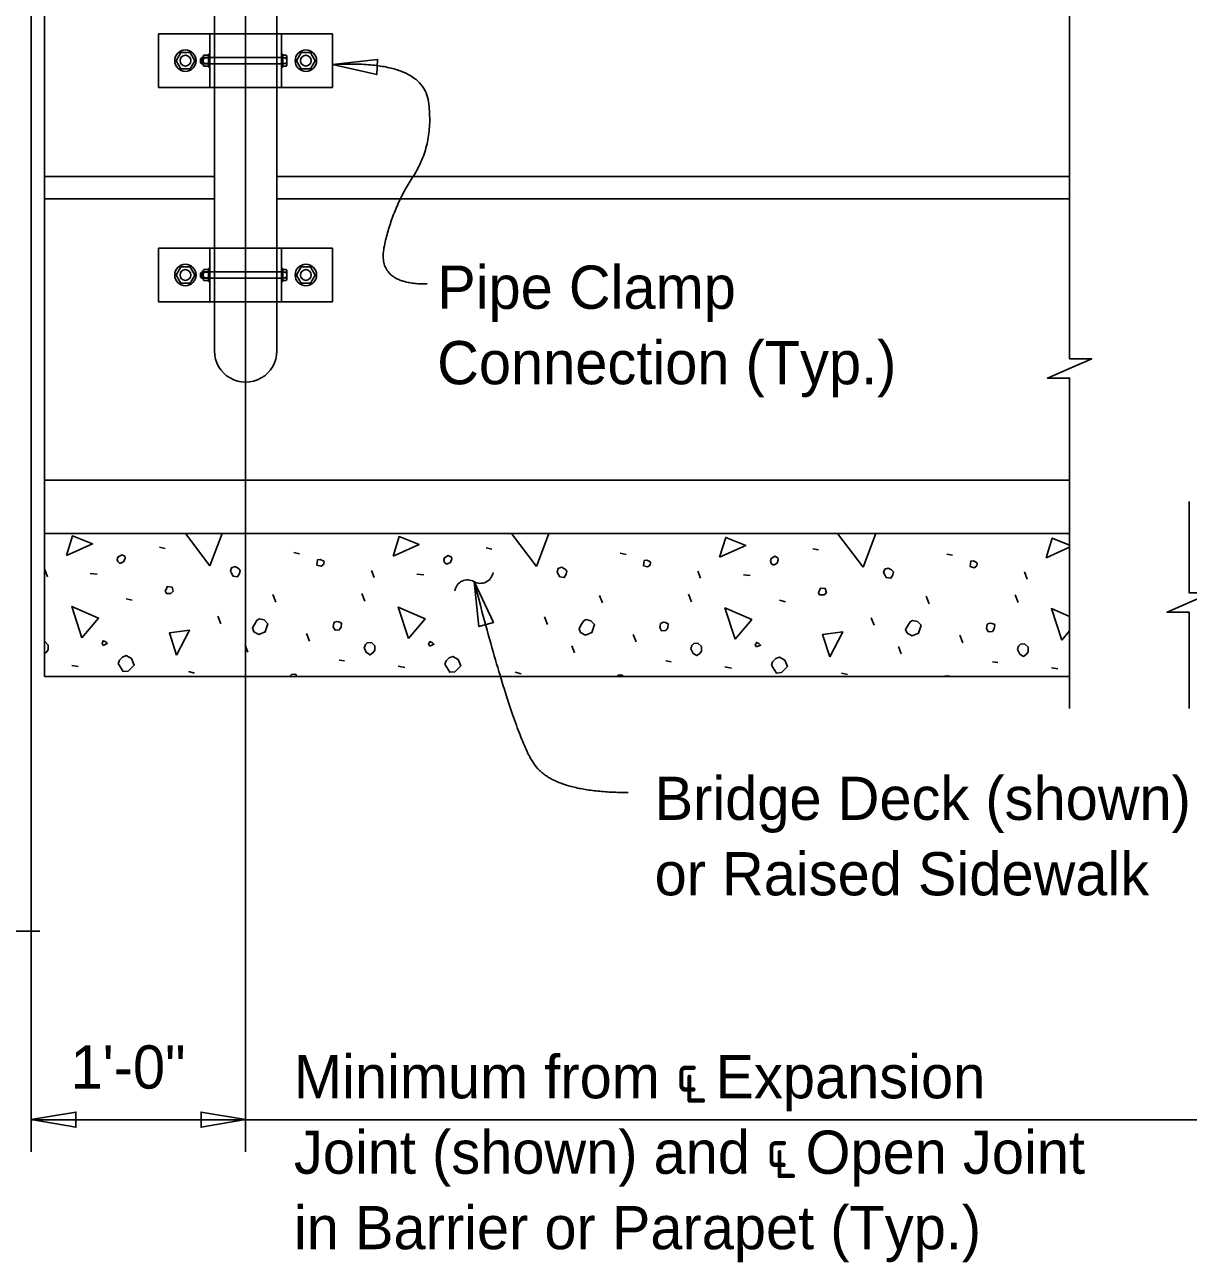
# Model space of a CAD drawing. Extents: x 0 to 41, y -96 to 25.
# Drawn here: x 23.58 to 29.01, y -84.93 to -79.16 of the extents above; entities that cross this region are included whole.
import ezdxf

# ---------------------------------------------------------------- set-up
doc = ezdxf.new("R2010")
doc.units = 0
for name, color, linetype in [('CL_Major', 7, 'Continuous'), ('Dimension', 7, 'Continuous'), ('Miscellaneous', 7, 'Continuous'), ('SteelMisc', 7, 'Continuous'), ('SteelMisc_h', 7, 'Continuous'), ('SupstrConc', 7, 'Continuous'), ('SupstrConc_h', 7, 'Continuous'), ('TextStructures', 7, 'Continuous')]:
    doc.layers.add(name, color=color, linetype=linetype)

msp = doc.modelspace()

# ---------------------------------------------------------------- linework, layer by layer
at = {"layer": 'CL_Major'}
for p, q in [((24.6151, -84.4142), (24.6151, -71.0824)), ((23.6151, -84.4142), (23.6151, -78.8563))]:
    msp.add_line(p, q, dxfattribs=at)
at = {"layer": 'Dimension'}
msp.add_line((23.6151, -84.2642), (29.4153, -84.2642), dxfattribs=at)
for points in [[(28.4596, -78.863), (28.4596, -80.7139), (28.5629, -80.7139), (28.4596, -80.7589), (28.3562, -80.8039), (28.4596, -80.8039), (28.4596, -82.3464)], [(29.0176, -81.3797), (29.0176, -81.8068), (29.1209, -81.8068), (29.0176, -81.8518), (28.9142, -81.8968), (29.0176, -81.8968), (29.0176, -82.3464)], [(23.6547, -83.3844), (22.9577, -83.3844), (22.9577, -83.5006), (22.8583, -83.2756), (22.8583, -83.3844), (22.2031, -83.3844)]]:
    msp.add_lwpolyline(points, dxfattribs=at)
for points in [[(25.0211, -79.3415), (25.2271, -79.3878), (25.2309, -79.3173)], [(25.6811, -81.7535), (25.7034, -81.9635), (25.7713, -81.9445)], [(23.6151, -84.2641), (23.8234, -84.2994), (23.8234, -84.2288)], [(24.6151, -84.2641), (24.4069, -84.2288), (24.4069, -84.2993)]]:
    msp.add_lwpolyline(points, close=True, dxfattribs=at)
for centre, start, end in [((25.6504, -81.8053), 59.84335, 171.57057), ((25.7103, -81.7023), 239.84335, 351.57057)]:
    msp.add_arc(centre, 0.0596, start, end, dxfattribs=at)
for points in [[(25.4627, -80.3651), (25.2257, -80.3674), (25.2971, -80.0162), (25.4956, -79.7112), (25.4402, -79.3184), (25.021, -79.3415)], [(26.3997, -82.7379), (26.0593, -82.7379), (25.8702, -82.4823), (25.6811, -81.7535)]]:
    msp.add_open_spline(points, degree=2, dxfattribs=at)
at = {"layer": 'Miscellaneous'}
for p, q in [((24.4075, -79.3301), (24.4075, -79.318)), ((24.4132, -79.3301), (24.4132, -79.318)), ((24.4075, -80.3301), (24.4075, -80.318)), ((24.4132, -80.3301), (24.4132, -80.318)), ((24.2137, -81.5934), (24.2402, -81.5987)), ((24.8395, -81.6181), (24.866, -81.6234)), ((25.7375, -81.5969), (25.7641, -81.6022)), ((26.3633, -81.6217), (26.3898, -81.627)), ((27.2613, -81.6005), (27.2879, -81.6058)), ((27.8871, -81.6252), (27.9137, -81.6305)), ((23.6905, -81.7313), (23.6781, -81.6977)), ((23.8902, -81.7154), (23.922, -81.7189)), ((25.2143, -81.7348), (25.2019, -81.7012)), ((25.414, -81.7189), (25.4459, -81.7224)), ((26.7381, -81.7384), (26.7257, -81.7048)), ((26.9378, -81.7224), (26.9697, -81.726)), ((28.2619, -81.7419), (28.2495, -81.7083)), ((24.7564, -81.8497), (24.7423, -81.8144)), ((25.1718, -81.8444), (25.1577, -81.8091)), ((26.6957, -81.848), (26.6815, -81.8126)), ((24.0582, -81.8338), (24.0864, -81.8409)), ((26.2802, -81.8533), (26.2661, -81.8179)), ((27.1058, -81.8409), (27.1341, -81.848)), ((27.8041, -81.8568), (27.7899, -81.8214)), ((28.2195, -81.8515), (28.2053, -81.8161)), ((24.5001, -81.9505), (24.486, -81.9151)), ((26.0239, -81.954), (26.0098, -81.9187)), ((27.5477, -81.9576), (27.5336, -81.9222)), ((24.9138, -82.0318), (24.8996, -81.9964)), ((26.4376, -82.0353), (26.4234, -82)), ((27.9614, -82.0389), (27.9472, -82.0035)), ((24.6256, -82.0831), (24.6132, -82.0495)), ((26.1494, -82.0866), (26.137, -82.053)), ((27.6732, -82.0901), (27.6609, -82.0566)), ((23.8036, -82.1449), (23.8336, -82.1502)), ((25.0516, -82.1202), (25.0764, -82.1237)), ((25.3274, -82.1485), (25.3575, -82.1538)), ((26.5755, -82.1237), (26.6002, -82.1273)), ((26.8512, -82.152), (26.8813, -82.1573)), ((28.0993, -82.1273), (28.124, -82.1308)), ((28.375, -82.1555), (28.4051, -82.1608)), ((24.3481, -82.1732), (24.3764, -82.1803)), ((25.8719, -82.1768), (25.9002, -82.1838)), ((27.3957, -82.1803), (27.424, -82.1874))]:
    msp.add_line(p, q, dxfattribs=at)
for points in [[(23.7788, -81.6323), (23.8071, -81.5404), (23.9008, -81.5775), (23.7788, -81.6323)], [(24.4488, -81.68), (24.3346, -81.5298)], [(24.505, -81.5298), (24.4488, -81.68)], [(25.3027, -81.6358), (25.3309, -81.5439), (25.4246, -81.581), (25.3027, -81.6358)], [(25.9726, -81.6836), (25.8558, -81.5298)], [(26.0301, -81.5298), (25.9726, -81.6836)], [(26.8265, -81.6394), (26.8548, -81.5474), (26.9485, -81.5846), (26.8265, -81.6394)], [(27.4965, -81.6871), (27.3769, -81.5298)], [(27.5553, -81.5298), (27.4965, -81.6871)], [(28.3503, -81.6429), (28.3786, -81.551), (28.4595, -81.583)], [(24.0263, -81.6676), (24.0334, -81.6676), (24.0475, -81.6606), (24.0529, -81.6447), (24.0511, -81.6358), (24.0369, -81.6288), (24.0193, -81.6394), (24.0157, -81.65), (24.0193, -81.6606), (24.0263, -81.6676)], [(25.5502, -81.6712), (25.5572, -81.6712), (25.5714, -81.6641), (25.5767, -81.6482), (25.5749, -81.6394), (25.5608, -81.6323), (25.5431, -81.6429), (25.5395, -81.6535), (25.5431, -81.6641), (25.5502, -81.6712)], [(27.074, -81.6747), (27.081, -81.6747), (27.0952, -81.6676), (27.1005, -81.6517), (27.0987, -81.6429), (27.0846, -81.6358), (27.0669, -81.6464), (27.0634, -81.657), (27.0669, -81.6676), (27.074, -81.6747)], [(28.4595, -81.5938), (28.3503, -81.6429)], [(24.5478, -81.7118), (24.5567, -81.7277), (24.5779, -81.7313), (24.5867, -81.7154), (24.5903, -81.7012), (24.5814, -81.6924), (24.5655, -81.6836), (24.5496, -81.6889), (24.5443, -81.7048), (24.5478, -81.7118)], [(24.9473, -81.6765), (24.9668, -81.6818), (24.9792, -81.6729), (24.9809, -81.6606), (24.9774, -81.657), (24.9633, -81.65), (24.9509, -81.6517), (24.9491, -81.6641), (24.9473, -81.6765)], [(26.0716, -81.7154), (26.0805, -81.7313), (26.1017, -81.7348), (26.1105, -81.7189), (26.1141, -81.7048), (26.1052, -81.6959), (26.0893, -81.6871), (26.0734, -81.6924), (26.0681, -81.7083), (26.0716, -81.7154)], [(26.4712, -81.68), (26.4906, -81.6853), (26.503, -81.6765), (26.5047, -81.6641), (26.5012, -81.6606), (26.4871, -81.6535), (26.4747, -81.6553), (26.4729, -81.6676), (26.4712, -81.68)], [(27.5955, -81.7189), (27.6043, -81.7348), (27.6255, -81.7384), (27.6343, -81.7224), (27.6379, -81.7083), (27.629, -81.6995), (27.6131, -81.6906), (27.5972, -81.6959), (27.5919, -81.7118), (27.5955, -81.7189)], [(27.995, -81.6836), (28.0144, -81.6889), (28.0268, -81.68), (28.0286, -81.6676), (28.025, -81.6641), (28.0109, -81.657), (27.9985, -81.6588), (27.9967, -81.6712), (27.995, -81.6836)], [(24.2455, -81.8091), (24.2668, -81.8091), (24.2774, -81.7985), (24.2721, -81.779), (24.2491, -81.7772), (24.2455, -81.7879), (24.2402, -81.7967), (24.2455, -81.8091), (24.242, -81.8055)], [(27.2932, -81.8161), (27.3144, -81.8161), (27.325, -81.8055), (27.3197, -81.7861), (27.2967, -81.7843), (27.2932, -81.7949), (27.2879, -81.8038), (27.2932, -81.8161), (27.2896, -81.8126)], [(23.8513, -82.0159), (23.8036, -81.8692), (23.9291, -81.924), (23.8513, -82.0159)], [(24.6539, -81.9876), (24.6769, -82), (24.7069, -81.9876), (24.7193, -81.9505), (24.7016, -81.9328), (24.6786, -81.9275), (24.668, -81.9346), (24.6557, -81.954), (24.6468, -81.9699), (24.6539, -81.9876)], [(25.3751, -82.0194), (25.3274, -81.8727), (25.4529, -81.9275), (25.3751, -82.0194)], [(26.899, -82.023), (26.8512, -81.8762), (26.9767, -81.931), (26.899, -82.023)], [(28.4228, -82.0265), (28.375, -81.8798), (28.4595, -81.9167)], [(28.9269, -81.8913), (28.9241, -81.8968)], [(24.2933, -82.0972), (24.2597, -81.9929), (24.3534, -81.9805), (24.2933, -82.0972)], [(25.0234, -81.9646), (25.0322, -81.9805), (25.0516, -81.9788), (25.0605, -81.9664), (25.0622, -81.9469), (25.0499, -81.9416), (25.041, -81.9399), (25.0304, -81.9434), (25.0269, -81.9469), (25.0234, -81.9646)], [(26.1777, -81.9911), (26.2007, -82.0035), (26.2307, -81.9911), (26.2431, -81.954), (26.2254, -81.9363), (26.2025, -81.931), (26.1919, -81.9381), (26.1795, -81.9576), (26.1706, -81.9735), (26.1777, -81.9911)], [(26.5472, -81.9682), (26.556, -81.9841), (26.5755, -81.9823), (26.5843, -81.9699), (26.5861, -81.9505), (26.5737, -81.9452), (26.5648, -81.9434), (26.5542, -81.9469), (26.5507, -81.9505), (26.5472, -81.9682)], [(27.7015, -81.9947), (27.7245, -82.0071), (27.7546, -81.9947), (27.7669, -81.9576), (27.7493, -81.9399), (27.7263, -81.9346), (27.7157, -81.9416), (27.7033, -81.9611), (27.6945, -81.977), (27.7015, -81.9947)], [(28.071, -81.9717), (28.0798, -81.9876), (28.0993, -81.9858), (28.1081, -81.9735), (28.1099, -81.954), (28.0975, -81.9487), (28.0887, -81.9469), (28.0781, -81.9505), (28.0745, -81.954), (28.071, -81.9717)], [(28.4595, -81.9831), (28.4228, -82.0265)], [(23.6763, -82.0893), (23.6869, -82.0813), (23.694, -82.0707), (23.694, -82.0495), (23.6781, -82.0336), (23.6763, -82.0337)], [(23.9503, -82.0512), (23.9698, -82.0424), (23.9627, -82.0353), (23.9503, -82.03), (23.945, -82.0424), (23.9503, -82.0512)], [(25.1683, -82.0636), (25.1789, -82.0848), (25.1966, -82.0954), (25.2107, -82.0848), (25.2178, -82.0742), (25.2178, -82.053), (25.2019, -82.0371), (25.1825, -82.0389), (25.1736, -82.0477), (25.1683, -82.0636)], [(25.4741, -82.0548), (25.4936, -82.0459), (25.4865, -82.0389), (25.4741, -82.0336), (25.4688, -82.0459), (25.4741, -82.0548)], [(26.6921, -82.0672), (26.7027, -82.0884), (26.7204, -82.099), (26.7346, -82.0884), (26.7416, -82.0778), (26.7416, -82.0566), (26.7257, -82.0406), (26.7063, -82.0424), (26.6974, -82.0512), (26.6921, -82.0672)], [(26.998, -82.0583), (27.0174, -82.0495), (27.0103, -82.0424), (26.998, -82.0371), (26.9926, -82.0495), (26.998, -82.0583)], [(27.3409, -82.1043), (27.3073, -82), (27.401, -81.9876), (27.3409, -82.1043)], [(28.2159, -82.0707), (28.2266, -82.0919), (28.2442, -82.1025), (28.2584, -82.0919), (28.2654, -82.0813), (28.2654, -82.0601), (28.2495, -82.0442), (28.2301, -82.0459), (28.2212, -82.0548), (28.2159, -82.0707)], [(24.021, -82.1361), (24.044, -82.1732), (24.067, -82.1715), (24.0758, -82.1626), (24.0953, -82.1432), (24.0829, -82.1131), (24.0582, -82.099), (24.0405, -82.106), (24.0263, -82.1202), (24.021, -82.1361)], [(25.5448, -82.1396), (25.5678, -82.1768), (25.5908, -82.175), (25.5996, -82.1662), (25.6191, -82.1467), (25.6067, -82.1167), (25.582, -82.1025), (25.5643, -82.1096), (25.5502, -82.1237), (25.5448, -82.1396)], [(27.0687, -82.1432), (27.0916, -82.1803), (27.1146, -82.1785), (27.1235, -82.1697), (27.1429, -82.1502), (27.1305, -82.1202), (27.1058, -82.106), (27.0881, -82.1131), (27.074, -82.1273), (27.0687, -82.1432)], [(24.8519, -82.1964), (24.8501, -82.1874), (24.8413, -82.1856), (24.8289, -82.1874), (24.8198, -82.1964)], [(26.375, -82.1964), (26.3739, -82.1909), (26.3651, -82.1891), (26.3527, -82.1909), (26.3472, -82.1964)], [(27.8981, -82.1964), (27.8977, -82.1944), (27.8889, -82.1927), (27.8765, -82.1944), (27.8745, -82.1964)]]:
    msp.add_lwpolyline(points, dxfattribs=at)
at = {"layer": 'SteelMisc'}
for p, q in [((24.4692, -79.1982), (24.4692, -72.8231)), ((24.7609, -79.1982), (24.7609, -72.8231)), ((24.2091, -79.1982), (25.021, -79.1982)), ((24.2091, -79.4482), (24.2091, -79.1982)), ((24.4484, -79.1982), (24.4484, -79.4482)), ((24.7817, -79.1982), (24.7817, -79.4482)), ((25.021, -79.1982), (25.021, -79.4482)), ((24.4047, -79.3152), (24.4103, -79.3086)), ((24.4047, -79.3329), (24.4047, -79.3152)), ((24.4103, -79.3086), (24.4168, -79.3086)), ((24.4103, -79.3385), (24.4103, -79.3086)), ((24.4168, -79.3053), (24.4168, -79.341)), ((24.4215, -79.3102), (24.4418, -79.3102)), ((24.4217, -79.2972), (24.4418, -79.2972)), ((24.4418, -79.2929), (24.4418, -79.3535)), ((24.4418, -79.2929), (24.4484, -79.2929)), ((24.4418, -79.2972), (24.4418, -79.3492)), ((24.788, -79.2929), (24.782, -79.2929)), ((24.788, -79.2929), (24.788, -79.3535)), ((24.8027, -79.2972), (24.788, -79.2972)), ((24.8028, -79.3102), (24.788, -79.3102)), ((24.8078, -79.3426), (24.8078, -79.3037)), ((24.4047, -79.3329), (24.4103, -79.3385)), ((24.4103, -79.3385), (24.4168, -79.3385)), ((24.4215, -79.3361), (24.4418, -79.3361)), ((24.4218, -79.3492), (24.4418, -79.3492)), ((24.4418, -79.3535), (24.4484, -79.3535)), ((24.788, -79.3535), (24.782, -79.3535)), ((24.8028, -79.3362), (24.788, -79.3362)), ((24.8027, -79.3492), (24.788, -79.3492)), ((25.021, -79.4482), (24.2091, -79.4482)), ((24.4692, -79.4482), (24.4692, -80.1982)), ((24.7609, -79.4482), (24.7609, -80.1982)), ((24.2091, -80.1982), (25.021, -80.1982)), ((24.2091, -80.4482), (24.2091, -80.1982)), ((24.4484, -80.1982), (24.4484, -80.4482)), ((24.7817, -80.1982), (24.7817, -80.4482)), ((25.021, -80.1982), (25.021, -80.4482)), ((24.4047, -80.3152), (24.4103, -80.3086)), ((24.4103, -80.3086), (24.4168, -80.3086)), ((24.4103, -80.3385), (24.4103, -80.3086)), ((24.4168, -80.3053), (24.4168, -80.341)), ((24.4215, -80.3102), (24.4418, -80.3102)), ((24.4217, -80.2972), (24.4418, -80.2972)), ((24.4418, -80.2929), (24.4418, -80.3535)), ((24.4418, -80.2929), (24.4484, -80.2929)), ((24.4418, -80.2972), (24.4418, -80.3492)), ((24.788, -80.2929), (24.782, -80.2929)), ((24.788, -80.2929), (24.788, -80.3535)), ((24.8027, -80.2972), (24.788, -80.2972)), ((24.8028, -80.3102), (24.788, -80.3102)), ((24.8078, -80.3426), (24.8078, -80.3037)), ((24.4047, -80.3329), (24.4047, -80.3152)), ((24.4047, -80.3329), (24.4103, -80.3385)), ((24.4103, -80.3385), (24.4168, -80.3385)), ((24.4215, -80.3361), (24.4418, -80.3361)), ((24.4218, -80.3492), (24.4418, -80.3492)), ((24.4418, -80.3535), (24.4484, -80.3535)), ((24.788, -80.3535), (24.782, -80.3535)), ((24.8028, -80.3362), (24.788, -80.3362)), ((24.8027, -80.3492), (24.788, -80.3492)), ((25.021, -80.4482), (24.2091, -80.4482)), ((24.4692, -80.4482), (24.4692, -80.6774)), ((24.7609, -80.6774), (24.7609, -80.4482))]:
    msp.add_line(p, q, dxfattribs=at)
for points in [[(24.3124, -79.2857), (24.3557, -79.2857), (24.3774, -79.3232), (24.3557, -79.3607), (24.3124, -79.3607), (24.2907, -79.3232)], [(24.8744, -79.2857), (24.9177, -79.2857), (24.9394, -79.3232), (24.9177, -79.3607), (24.8744, -79.3607), (24.8527, -79.3232)], [(24.3124, -80.2857), (24.3557, -80.2857), (24.3774, -80.3232), (24.3557, -80.3607), (24.3124, -80.3607), (24.2907, -80.3232)], [(24.8744, -80.2857), (24.9177, -80.2857), (24.9394, -80.3232), (24.9177, -80.3607), (24.8744, -80.3607), (24.8527, -80.3232)]]:
    msp.add_lwpolyline(points, close=True, dxfattribs=at)
for centre, radius in [((24.3341, -79.3232), 0.05), ((24.896, -79.3232), 0.05), ((24.3341, -79.3232), 0.025), ((24.896, -79.3232), 0.025), ((24.3341, -80.3232), 0.05), ((24.3341, -80.3232), 0.025), ((24.896, -80.3232), 0.05), ((24.896, -80.3232), 0.025)]:
    msp.add_circle(centre, radius, dxfattribs=at)
for centre, radius, start, end in [((24.4234, -79.3038), 0.00674, 104.48908, 254.18889), ((24.4363, -79.3232), 0.0196, 138.62797, 221.37203), ((24.801, -79.3038), 0.00673, 285.7823, 75.54039), ((24.7881, -79.3232), 0.0196, 318.62797, 41.37203), ((24.4234, -79.3427), 0.00673, 105.7823, 255.54039), ((24.801, -79.3427), 0.00674, 284.48908, 74.18889), ((24.4234, -80.3038), 0.00674, 104.48908, 254.18889), ((24.4363, -80.3232), 0.0196, 138.62797, 221.37203), ((24.801, -80.3038), 0.00673, 285.7823, 75.54039), ((24.7881, -80.3232), 0.0196, 318.62797, 41.37203), ((24.4234, -80.3427), 0.00673, 105.7823, 255.54039), ((24.801, -80.3427), 0.00674, 284.48908, 74.18889)]:
    msp.add_arc(centre, radius, start, end, dxfattribs=at)
msp.add_ellipse((24.6151, -80.6774), major_axis=(0, 0.1458), ratio=0.999499, start_param=1.570796, end_param=4.712389, dxfattribs=at)
at = {"layer": 'SteelMisc_h'}
for p, q in [((24.4692, -79.1982), (24.4692, -79.4482)), ((24.7609, -79.1982), (24.7609, -79.4482)), ((24.7817, -79.3086), (24.4168, -79.3086)), ((24.4168, -79.3385), (24.7817, -79.3385)), ((24.4692, -80.1982), (24.4692, -80.4482)), ((24.7609, -80.1982), (24.7609, -80.4482)), ((24.7817, -80.3086), (24.4168, -80.3086)), ((24.4168, -80.3385), (24.7817, -80.3385))]:
    msp.add_line(p, q, dxfattribs=at)
at = {"layer": 'SupstrConc'}
for p, q in [((23.6763, -78.8631), (23.6763, -82.1964)), ((23.6763, -79.8631), (24.4692, -79.8631)), ((24.7609, -79.8631), (28.4595, -79.8631)), ((24.7609, -79.8631), (26.002, -79.8631)), ((23.6763, -79.9673), (24.4692, -79.9673)), ((24.7609, -79.9673), (28.4595, -79.9673)), ((24.7609, -79.9673), (26.002, -79.9673)), ((23.6763, -81.5298), (28.4595, -81.5298)), ((23.6763, -82.1964), (28.4595, -82.1964))]:
    msp.add_line(p, q, dxfattribs=at)
at = {"layer": 'SupstrConc_h'}
msp.add_line((23.6763, -81.2797), (28.4595, -81.2797), dxfattribs=at)

# ---------------------------------------------------------------- texts
at = {"layer": 'Dimension'}
for s, p in [('Pipe Clamp ', (25.5087, -80.481)), ('Connection (Typ.)', (25.5087, -80.833)), ('Bridge Deck (shown)', (26.5232, -82.8656)), ('or Raised Sidewalk', (26.5232, -83.2176)), ('Minimum from ℄ Expansion', (24.8405, -84.1646)), ('Joint (shown) and ℄ Open Joint ', (24.8405, -84.5166)), ('in Barrier or Parapet (Typ.)', (24.8405, -84.8686))]:
    msp.add_text(s, height=0.2016, dxfattribs=at).set_placement(p)
at = {"layer": 'TextStructures'}
msp.add_text('1\'-0"', height=0.2016, dxfattribs=at).set_placement((23.7982, -84.1191))

doc.saveas('drawing.dxf')
